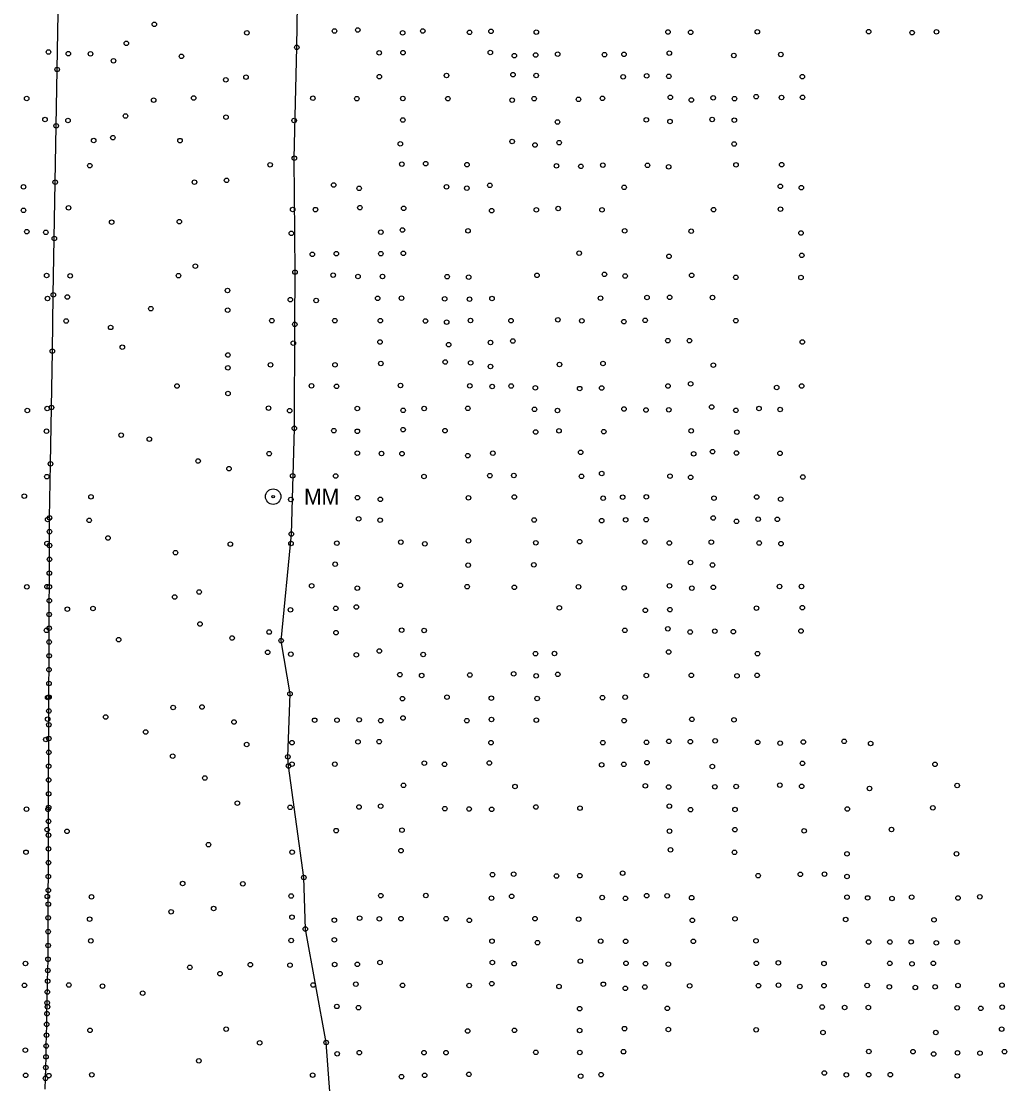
# Model space of a CAD drawing. Extents: x 20503438 to 20508873, y 7964251 to 7984667.
# Drawn here: x 20506676.3 to 20507113.2, y 7971655.2 to 7972126.6 of the extents above; entities that cross this region are included whole.
import ezdxf

# ---------------------------------------------------------------- set-up
doc = ezdxf.new("R2010")
doc.units = 0
for name, color, linetype in [('SurDrainageArrowDown', 7, 'Continuous'), ('SurRoadPoints', 7, 'Continuous'), ('SurSurveyPoints', 7, 'Continuous')]:
    doc.layers.add(name, color=color, linetype=linetype)

msp = doc.modelspace()

# ---------------------------------------------------------------- linework, layer by layer
at = {"layer": 'SurDrainageArrowDown'}
for points in [[(20506813.22, 7971649.77), (20506811.45, 7971673.51), (20506802.24, 7971723.86), (20506801.55, 7971746.7), (20506794.77, 7971796.23), (20506794.48, 7971800.28), (20506795.43, 7971828.21), (20506791.47, 7971851.77), (20506796.03, 7971899.11), (20506797.36, 7971945.99), (20506797.53, 7971992.11), (20506797.66, 7972015.31), (20506797.31, 7972065.83), (20506798.41, 7972115.04), (20506799.16, 7972162.84)], [(20506686.9, 7971652.84), (20506687.01, 7971657.62), (20506687.11, 7971662.41), (20506687.22, 7971667.2), (20506687.32, 7971671.99), (20506687.42, 7971676.77), (20506687.53, 7971681.56), (20506687.63, 7971686.35), (20506687.74, 7971691.14), (20506687.94, 7971700.71), (20506688.05, 7971705.5), (20506688.14, 7971710.46), (20506688.16, 7971716.58), (20506688.18, 7971722.7), (20506688.22, 7971734.93), (20506688.24, 7971741.05), (20506688.27, 7971747.17), (20506688.29, 7971753.29), (20506688.31, 7971759.41), (20506688.37, 7971777.77), (20506688.39, 7971783.88), (20506688.47, 7971808.36), (20506688.51, 7971820.6), (20506688.53, 7971826.71), (20506688.55, 7971832.83), (20506688.58, 7971838.95), (20506688.66, 7971863.43), (20506688.68, 7971869.54), (20506688.7, 7971875.66), (20506688.78, 7971900.14), (20506688.8, 7971906.26), (20506689.2, 7971930.24), (20506689.62, 7971955.24), (20506690.04, 7971980.23), (20506690.47, 7972005.23), (20506690.89, 7972030.22), (20506691.31, 7972055.22), (20506692.15, 7972105.21), (20506693.01, 7972155.2)]]:
    msp.add_lwpolyline(points, dxfattribs=at)
at = {"layer": 'SurRoadPoints'}
for radius in [3.43, 0.571]:
    msp.add_circle((20506787.95, 7971915.7), radius, dxfattribs=at)
at = {"layer": 'SurSurveyPoints'}
for centre in [(20506735.23, 7972125.23), (20506776.31, 7972121.47), (20506815.15, 7972122.3), (20506825.46, 7972122.74), (20506845.34, 7972121.44), (20506854.29, 7972122.28), (20506875.03, 7972121.68), (20506884.53, 7972122.09), (20506904.63, 7972121.79), (20506963, 7972121.8), (20506973.04, 7972121.7), (20507002.61, 7972121.93), (20507051.98, 7972122), (20507071.26, 7972121.55), (20507082.04, 7972121.89), (20506722.84, 7972116.8), (20506688.33, 7972112.95), (20506697.11, 7972112.23), (20506706.96, 7972112.13), (20506747.28, 7972111.02), (20506798.41, 7972115.04), (20506834.97, 7972112.55), (20506845.52, 7972112.63), (20506884.24, 7972112.75), (20506894.89, 7972111.33), (20506904.34, 7972111.63), (20506914.1, 7972111.99), (20506934.85, 7972111.8), (20506943.5, 7972111.92), (20506963.61, 7972112.47), (20506992.2, 7972111.42), (20507013.07, 7972111.88), (20506717.16, 7972109.07), (20506692.15, 7972105.21), (20506775.89, 7972101.82), (20506835.02, 7972102.03), (20506864.83, 7972102.51), (20506894.26, 7972102.91), (20506904.59, 7972102.53), (20506943.15, 7972101.93), (20506953.58, 7972102.38), (20506963.4, 7972102.14), (20507022.6, 7972102.04), (20506766.93, 7972100.59), (20506678.67, 7972092.31), (20506734.95, 7972091.62), (20506752.71, 7972092.57), (20506805.57, 7972092.45), (20506825.04, 7972092.23), (20506845.45, 7972092.36), (20506865.42, 7972092.28), (20506893.92, 7972091.61), (20506903.66, 7972092.24), (20506923.34, 7972091.93), (20506933.95, 7972092.37), (20506964.06, 7972092.84), (20506973.34, 7972091.69), (20506983.07, 7972092.63), (20506992.5, 7972092.28), (20507002.11, 7972093.11), (20507013.37, 7972092.77), (20507022.69, 7972092.84), (20506686.79, 7972082.98), (20506696.95, 7972082.56), (20506722.46, 7972084.56), (20506767.04, 7972084.03), (20506797.24, 7972082.55), (20506845.44, 7972082.76), (20506953.38, 7972082.84), (20506982.59, 7972083.03), (20506992.43, 7972082.69), (20506691.73, 7972080.21), (20506914.02, 7972081.93), (20506963.9, 7972082.09), (20506708.38, 7972073.67), (20506716.88, 7972074.94), (20506746.63, 7972073.65), (20506893.9, 7972073.25), (20506914.78, 7972072.7), (20506844.33, 7972072.23), (20506904.03, 7972071.7), (20506992.34, 7972072.16), (20506797.31, 7972065.83), (20506855.6, 7972063.43), (20506706.62, 7972062.55), (20506786.59, 7972062.92), (20506845, 7972063.22), (20506873.92, 7972062.96), (20506913.56, 7972062.42), (20506924.39, 7972062.2), (20506934.11, 7972062.77), (20506953.92, 7972062.69), (20506963.31, 7972062.04), (20506993.15, 7972062.86), (20507013.45, 7972062.99), (20506691.31, 7972055.22), (20506753.04, 7972055.22), (20506767.28, 7972056.02), (20506814.77, 7972053.97), (20506677.25, 7972053.11), (20506826.09, 7972052.49), (20506864.79, 7972053.15), (20506873.82, 7972052.55), (20506884.01, 7972053.79), (20506943.59, 7972052.93), (20507012.84, 7972053.34), (20507022.12, 7972052.78), (20506677.25, 7972042.72), (20506697.22, 7972043.81), (20506796.59, 7972043.06), (20506806.68, 7972043.04), (20506826.4, 7972043.89), (20506845.79, 7972043.61), (20506884.82, 7972042.56), (20506904.65, 7972042.93), (20506914.35, 7972043.5), (20506933.75, 7972042.92), (20506983.23, 7972043.03), (20507012.88, 7972043.24), (20506716.32, 7972037.44), (20506746.36, 7972037.67), (20506678.69, 7972033.23), (20506687.16, 7972032.94), (20506795.99, 7972032.49), (20506835.69, 7972033.03), (20506845.26, 7972033.97), (20506874.33, 7972033.65), (20506943.83, 7972033.63), (20506973.32, 7972033.44), (20507022, 7972032.64), (20506690.89, 7972030.22), (20506805.3, 7972023.18), (20506815.97, 7972023.51), (20506835.67, 7972023.5), (20506845.65, 7972023.62), (20506923.65, 7972023.69), (20506963.43, 7972022.32), (20507022.34, 7972022.75), (20506753.45, 7972017.94), (20506687.49, 7972013.81), (20506697.96, 7972013.63), (20506745.96, 7972013.71), (20506797.66, 7972015.31), (20506797.66, 7972015.31), (20506814.55, 7972013.98), (20506825.56, 7972013.35), (20506836.41, 7972013.39), (20506865.11, 7972013.28), (20506874.64, 7972013.08), (20506904.9, 7972013.89), (20506934.83, 7972014.29), (20506944.03, 7972013.59), (20506973.51, 7972013.87), (20506993.1, 7972012.98), (20507021.96, 7972012.91), (20506767.73, 7972007.15), (20506687.91, 7972003.56), (20506690.47, 7972005.23), (20506696.66, 7972004.24), (20506795.59, 7972003.1), (20506807, 7972002.71), (20506834.29, 7972003.7), (20506844.86, 7972003.73), (20506864, 7972003.45), (20506875.04, 7972003.28), (20506884.96, 7972003.56), (20506933.11, 7972003.74), (20506953.73, 7972004.05), (20506963.78, 7972004.14), (20506982.75, 7972004.01), (20506733.69, 7971999.07), (20506767.8, 7971998.44), (20506696.15, 7971993.62), (20506787.37, 7971993.74), (20506815.29, 7971993.77), (20506835.48, 7971993.75), (20506855.46, 7971993.64), (20506864.86, 7971993.12), (20506875.46, 7971993.81), (20506893.4, 7971993.74), (20506914.2, 7971994.16), (20506924.79, 7971993.7), (20506943.47, 7971993.35), (20506952.89, 7971993.89), (20506993.08, 7971993.77), (20506715.87, 7971990.77), (20506797.53, 7971992.11), (20506796.86, 7971983.8), (20506835.31, 7971984.28), (20506884.32, 7971984.04), (20506894.21, 7971984.73), (20506962.93, 7971984.86), (20506972.53, 7971984.92), (20507022.55, 7971984.32), (20506690.04, 7971980.23), (20506721.06, 7971981.98), (20506767.87, 7971978.5), (20506865.75, 7971983.11), (20506786.8, 7971974.15), (20506815.34, 7971974.16), (20506835.68, 7971974.79), (20506864.25, 7971975.42), (20506875.49, 7971975.05), (20506914.89, 7971974.31), (20506934.19, 7971974.76), (20506983.14, 7971974.04), (20506767.88, 7971972.82), (20506884.28, 7971973.44), (20506745.28, 7971964.75), (20506804.95, 7971964.84), (20506816.06, 7971964.64), (20506844.39, 7971965.03), (20506875.13, 7971964.83), (20506885.09, 7971964.52), (20506893.48, 7971964.75), (20506963.01, 7971964.8), (20506973.07, 7971965.74), (20507022.32, 7971964.79), (20506767.91, 7971961.46), (20506904.2, 7971963.97), (20506923.86, 7971963.63), (20506933.58, 7971963.86), (20507011.21, 7971964.11), (20506689.62, 7971955.24), (20506785.9, 7971954.97), (20506874.26, 7971954.88), (20506982.38, 7971955.47), (20506678.94, 7971953.89), (20506687.77, 7971954.77), (20506795.28, 7971953.82), (20506825.24, 7971954.8), (20506845.61, 7971953.98), (20506854.9, 7971954.77), (20506903.81, 7971954.42), (20506913.99, 7971953.88), (20506943.53, 7971954.58), (20506953.27, 7971954.11), (20506963.36, 7971954.24), (20506993.12, 7971953.98), (20507003.4, 7971954.76), (20507012.72, 7971954.33), (20506797.36, 7971945.99), (20506687.46, 7971944.72), (20506720.54, 7971942.99), (20506733.06, 7971941.23), (20506814.86, 7971944.97), (20506825.28, 7971944.7), (20506845.57, 7971945.4), (20506864.11, 7971944.97), (20506904.37, 7971944.4), (20506914.69, 7971944.92), (20506934.53, 7971944.55), (20506973.33, 7971944.85), (20506993.58, 7971944.32), (20506754.67, 7971931.49), (20506786.18, 7971934.74), (20506825.25, 7971935), (20506835.97, 7971934.8), (20506845.1, 7971934.73), (20506874.23, 7971933.88), (20506885.35, 7971934.99), (20506924.28, 7971935.36), (20506974.4, 7971934.71), (20506982.78, 7971935.64), (20506993.37, 7971935.03), (20507012.66, 7971934.92), (20506689.2, 7971930.24), (20506768.35, 7971928.09), (20506687.57, 7971924.54), (20506796.62, 7971924.95), (20506815.67, 7971924.87), (20506854.85, 7971924.64), (20506884.03, 7971925.01), (20506894.68, 7971925.09), (20506924.68, 7971924.73), (20506933.64, 7971925.97), (20506963.88, 7971924.76), (20506973.04, 7971924.25), (20507022.8, 7971924.39), (20506677.58, 7971915.94), (20506707.18, 7971915.63), (20506795.79, 7971914.44), (20506825.32, 7971915.23), (20506835.44, 7971914.52), (20506874.54, 7971915.16), (20506894.86, 7971915.53), (20506934.27, 7971914.98), (20506942.92, 7971915.43), (20506953.41, 7971915.57), (20506983.44, 7971915.03), (20507002.36, 7971915.53), (20507012.95, 7971914.56), (20506687.94, 7971905.54), (20506688.8, 7971906.26), (20506706.39, 7971905.19), (20506825.88, 7971905.83), (20506835.37, 7971905.24), (20506903.66, 7971905.34), (20506933.64, 7971905.01), (20506944.28, 7971905.38), (20506953.35, 7971905.45), (20506983.08, 7971906.22), (20506993.41, 7971904.73), (20507003.02, 7971905.68), (20507011.5, 7971905.62), (20506688.78, 7971900.14), (20506796.03, 7971899.11), (20506687.65, 7971894.9), (20506688.76, 7971894.02), (20506714.74, 7971897.34), (20506768.98, 7971894.64), (20506795.87, 7971894.93), (20506816.2, 7971895.04), (20506844.57, 7971895.52), (20506855.2, 7971894.74), (20506874.57, 7971896.09), (20506904.38, 7971895.23), (20506923.88, 7971895.75), (20506952.78, 7971895.6), (20506963.64, 7971895.14), (20506982.2, 7971895.5), (20507003.46, 7971895.11), (20507013.14, 7971894.86), (20506744.63, 7971890.83), (20506688.74, 7971887.9), (20506815.44, 7971885.71), (20506874.41, 7971885.28), (20506903.52, 7971885.45), (20506972.97, 7971886.45), (20506982.74, 7971885.38), (20506688.72, 7971881.78), (20506678.72, 7971875.65), (20506687.67, 7971875.78), (20506688.7, 7971875.66), (20506804.99, 7971876.11), (20506825.25, 7971875.12), (20506844.36, 7971876.33), (20506873.96, 7971875.74), (20506894.9, 7971875.46), (20506923.32, 7971875.68), (20506943.58, 7971875.2), (20506963.65, 7971876.12), (20506973.57, 7971875.12), (20506983.13, 7971875.45), (20507012.49, 7971875.81), (20507022.21, 7971875.85), (20506744.28, 7971871.16), (20506755.15, 7971873.39), (20506688.68, 7971869.54), (20506696.7, 7971865.75), (20506708.05, 7971866.08), (20506795.61, 7971865.49), (20506815.71, 7971866.13), (20506824.8, 7971866.75), (20506914.85, 7971866.38), (20506963.86, 7971865.52), (20507002.23, 7971866.24), (20507022.58, 7971866.42), (20506688.66, 7971863.43), (20506953, 7971865.25), (20506687.44, 7971856.39), (20506688.64, 7971857.31), (20506755.48, 7971859.21), (20506844.95, 7971856.42), (20506854.88, 7971856.34), (20506943.89, 7971856.36), (20506962.94, 7971857.08), (20506983.76, 7971856.04), (20507022, 7971856.07), (20506688.62, 7971851.19), (20506719.46, 7971852.24), (20506769.73, 7971852.95), (20506786.19, 7971855.61), (20506791.47, 7971851.77), (20506815.8, 7971855.37), (20506972.85, 7971855.64), (20506991.97, 7971855.76), (20506785.5, 7971846.65), (20506835.04, 7971847.2), (20506963.33, 7971846.74), (20506688.6, 7971845.07), (20506795.77, 7971845.8), (20506824.83, 7971845.5), (20506854.49, 7971845.65), (20506904.26, 7971846), (20506912.66, 7971846.07), (20507002.72, 7971846.01), (20506688.58, 7971838.95), (20506894.59, 7971837.07), (20506688.55, 7971832.83), (20506844.15, 7971836.69), (20506853.81, 7971836.31), (20506875.17, 7971836.59), (20506904.55, 7971836.17), (20506914.14, 7971836.84), (20506953.4, 7971836.34), (20506973.39, 7971836.42), (20506993.6, 7971836.18), (20507002.53, 7971836.42), (20506795.43, 7971828.21), (20506687.96, 7971826.6), (20506688.53, 7971826.71), (20506845.26, 7971826.07), (20506865.04, 7971826.75), (20506884.7, 7971826.26), (20506904.98, 7971826.16), (20506933.99, 7971826.51), (20506944.03, 7971826.72), (20506688.51, 7971820.6), (20506743.58, 7971822.14), (20506756.36, 7971822.34), (20506687.95, 7971816.94), (20506688.49, 7971814.48), (20506713.67, 7971817.95), (20506770.56, 7971815.71), (20506806.32, 7971816.49), (20506816.25, 7971816.53), (20506826.05, 7971816.66), (20506835.65, 7971816.32), (20506845.55, 7971817.48), (20506873.84, 7971816.3), (20506884.73, 7971816.84), (20506904.66, 7971816.55), (20506943.55, 7971816.31), (20506973.62, 7971816.91), (20506992.29, 7971816.66), (20506731.39, 7971811.28), (20506687.18, 7971807.94), (20506688.47, 7971808.36), (20506776.21, 7971805.73), (20506796.28, 7971806.55), (20506825.55, 7971806.9), (20506834.94, 7971807), (20506884.56, 7971806.53), (20506934.14, 7971806.55), (20506953.5, 7971806.72), (20506963.42, 7971807.13), (20506972.92, 7971806.97), (20506983.95, 7971807.35), (20507002.8, 7971806.71), (20507012.75, 7971806.34), (20507023.03, 7971806.85), (20507041.13, 7971807.13), (20507052.86, 7971806.2), (20506688.45, 7971802.24), (20506743.39, 7971800.54), (20506794.48, 7971800.28), (20506688.43, 7971796.12), (20506794.77, 7971796.23), (20506796.33, 7971797.01), (20506815.28, 7971797), (20506854.96, 7971797.47), (20506863.95, 7971796.92), (20506883.79, 7971797.51), (20506933.59, 7971796.74), (20506943.44, 7971796.91), (20506953.72, 7971797.7), (20506982.68, 7971795.97), (20507022.63, 7971797.38), (20507081.43, 7971796.96), (20506688.41, 7971790), (20506757.64, 7971790.84), (20506845.72, 7971787.63), (20506895.2, 7971787.08), (20506953, 7971787.43), (20506963.32, 7971786.87), (20506983.82, 7971786.99), (20506993.21, 7971787.12), (20507012.6, 7971787.72), (20507022.31, 7971787.15), (20507052.36, 7971786.24), (20507091.23, 7971787.56), (20506688.39, 7971783.88), (20506678.57, 7971777.03), (20506688.12, 7971776.98), (20506688.37, 7971777.77), (20506772.08, 7971779.69), (20506795.49, 7971777.88), (20506826.04, 7971778.03), (20506835.62, 7971778.37), (20506864.05, 7971777.28), (20506874.82, 7971777.14), (20506884.85, 7971776.98), (20506904.44, 7971778.03), (20506924.03, 7971777.52), (20506963.61, 7971778.41), (20506973.02, 7971776.84), (20506992.73, 7971776.87), (20507042.52, 7971777.11), (20507080.45, 7971777.64), (20506688.35, 7971771.65), (20506687.77, 7971767.92), (20506696.54, 7971767.21), (20506815.9, 7971767.54), (20506845.04, 7971767.73), (20506963.68, 7971767.32), (20506992.69, 7971767.92), (20507023.36, 7971767.41), (20507062.13, 7971768), (20506688.33, 7971765.53), (20506678.37, 7971757.93), (20506688.31, 7971759.41), (20506759.29, 7971761.29), (20506796.35, 7971757.98), (20506844.65, 7971758.66), (20506964.14, 7971759.01), (20506992.49, 7971757.89), (20507042.37, 7971757.24), (20507090.94, 7971757.24), (20506688.29, 7971753.29), (20506885.2, 7971747.99), (20506894.61, 7971748.2), (20506923.9, 7971747.51), (20506942.9, 7971748.69), (20507003.02, 7971747.52), (20507021.72, 7971748.14), (20507032.41, 7971748.23), (20506688.27, 7971747.17), (20506747.79, 7971744.03), (20506774.51, 7971743.93), (20506801.55, 7971746.7), (20506913.59, 7971747.42), (20507042.4, 7971747.19), (20506687.82, 7971738.34), (20506688.24, 7971741.05), (20506707.39, 7971738.13), (20506795.94, 7971738.51), (20506835.66, 7971738.67), (20506855.64, 7971738.71), (20506893.68, 7971738.35), (20506953.55, 7971738.69), (20506962.67, 7971738.61), (20507101.27, 7971738.19), (20506688.22, 7971734.93), (20506884.72, 7971737.57), (20506933.84, 7971737.83), (20506944.14, 7971737.5), (20506973.48, 7971737.75), (20507042.38, 7971738.02), (20507051.54, 7971737.67), (20507062.33, 7971737.44), (20507071.09, 7971737.99), (20507091.59, 7971737.63), (20506688.2, 7971728.82), (20506742.69, 7971731.53), (20506761.54, 7971732.94), (20506796.31, 7971729.1), (20506826.27, 7971728.67), (20506706.55, 7971728.21), (20506815.1, 7971727.77), (20506835.04, 7971728.39), (20506844.62, 7971728.47), (20506864.67, 7971728.44), (20506874.94, 7971727.72), (20506904.04, 7971728.45), (20506923.42, 7971728.21), (20506973.83, 7971727.71), (20506992.76, 7971728.4), (20507041.8, 7971728.07), (20507080.95, 7971727.96), (20506688.18, 7971722.7), (20506802.24, 7971723.86), (20506688.16, 7971716.58), (20506707.1, 7971718.61), (20506795.95, 7971718.78), (20506815.09, 7971719.08), (20506884.95, 7971718.45), (20506905.16, 7971717.79), (20506933.17, 7971718.52), (20506944.24, 7971718.44), (20506974.24, 7971718.44), (20507002.06, 7971718.62), (20507051.97, 7971718.1), (20507061.41, 7971718.09), (20507070.81, 7971718.15), (20507082, 7971717.76), (20507091.2, 7971718.04), (20506688.14, 7971710.46), (20506678.11, 7971708.59), (20506688.05, 7971705.5), (20506751.01, 7971706.87), (20506777.81, 7971708.08), (20506795.4, 7971707.83), (20506815.21, 7971708.17), (20506825.29, 7971708.23), (20506835.33, 7971709.02), (20506885.15, 7971709.03), (20506894.83, 7971708.47), (20506924.18, 7971709.64), (20506944.38, 7971708.64), (20506953.08, 7971708.48), (20506963.18, 7971708.29), (20507002.17, 7971708.65), (20507011.96, 7971708.85), (20507032.17, 7971708.54), (20507061.35, 7971708.62), (20507071.24, 7971708.42), (20507080.7, 7971708.67), (20506687.94, 7971700.71), (20506764.36, 7971704.04), (20506677.65, 7971698.91), (20506687.84, 7971695.93), (20506697.36, 7971699.07), (20506712.29, 7971698.55), (20506805.67, 7971699.04), (20506824.6, 7971699.41), (20506845.32, 7971698.88), (20506874.89, 7971698.83), (20506884.88, 7971699.64), (20506914.72, 7971698.4), (20506934.34, 7971699.37), (20506944.1, 7971697.55), (20506952.76, 7971698.16), (20506972.64, 7971698.66), (20507003.12, 7971698.76), (20507012, 7971698.96), (20507021.5, 7971698.41), (20507032.2, 7971698.74), (20507051.33, 7971698.8), (20507061.18, 7971698.19), (20507072.66, 7971697.96), (20507081.46, 7971698.19), (20507091.6, 7971698.84), (20507111.1, 7971698.99), (20506687.74, 7971691.14), (20506730.1, 7971695.4), (20506687.63, 7971686.35), (20506687.92, 7971689.37), (20506816.16, 7971689.54), (20506825.78, 7971688.99), (20506923.82, 7971688.57), (20506962.71, 7971688.67), (20507031.39, 7971689.31), (20507041.34, 7971689.04), (20507051.88, 7971689.05), (20507091.27, 7971688.93), (20507101.71, 7971688.67), (20507111.22, 7971689.24), (20506687.53, 7971681.56), (20506687.42, 7971676.77), (20506706.74, 7971678.9), (20506767.1, 7971679.47), (20506874.19, 7971678.62), (20506894.93, 7971678.95), (20506923.83, 7971678.89), (20506943.72, 7971679.7), (20506963.19, 7971679.31), (20507002.11, 7971679.18), (20507031.74, 7971677.97), (20507081.75, 7971677.94), (20507110.96, 7971679.47), (20506781.97, 7971673.4), (20506811.45, 7971673.51), (20506678.07, 7971670.13), (20506687.32, 7971671.99), (20506816.36, 7971668.54), (20506826.12, 7971669.04), (20506854.82, 7971669), (20506864.6, 7971669.05), (20506904.4, 7971669.15), (20506923.89, 7971669.12), (20506943.28, 7971669.43), (20507052.04, 7971669.54), (20507071.68, 7971669.46), (20507080.79, 7971668.45), (20507091.39, 7971668.92), (20507101.38, 7971668.79), (20507112.22, 7971669.48), (20506687.22, 7971667.2), (20506755, 7971665.38), (20506678.21, 7971658.97), (20506687.11, 7971662.41), (20506688.45, 7971658.85), (20506707.52, 7971659.22), (20506805.46, 7971659.07), (20506844.86, 7971658.4), (20506855.13, 7971658.95), (20506874.74, 7971659.38), (20506924.33, 7971658.6), (20506933.36, 7971659.28), (20507032.37, 7971660), (20507042.09, 7971659.16), (20507052.02, 7971659.26), (20507061.57, 7971659.25), (20507091.34, 7971658.78), (20506687.01, 7971657.62)]:
    msp.add_circle(centre, 1, dxfattribs=at)

# ---------------------------------------------------------------- texts
at = {"layer": 'SurRoadPoints'}
msp.add_text('MM', height=6.995, rotation=360, dxfattribs=at).set_placement((20506801.66, 7971912.2))

doc.saveas('drawing.dxf')
